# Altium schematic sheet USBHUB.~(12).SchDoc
size A
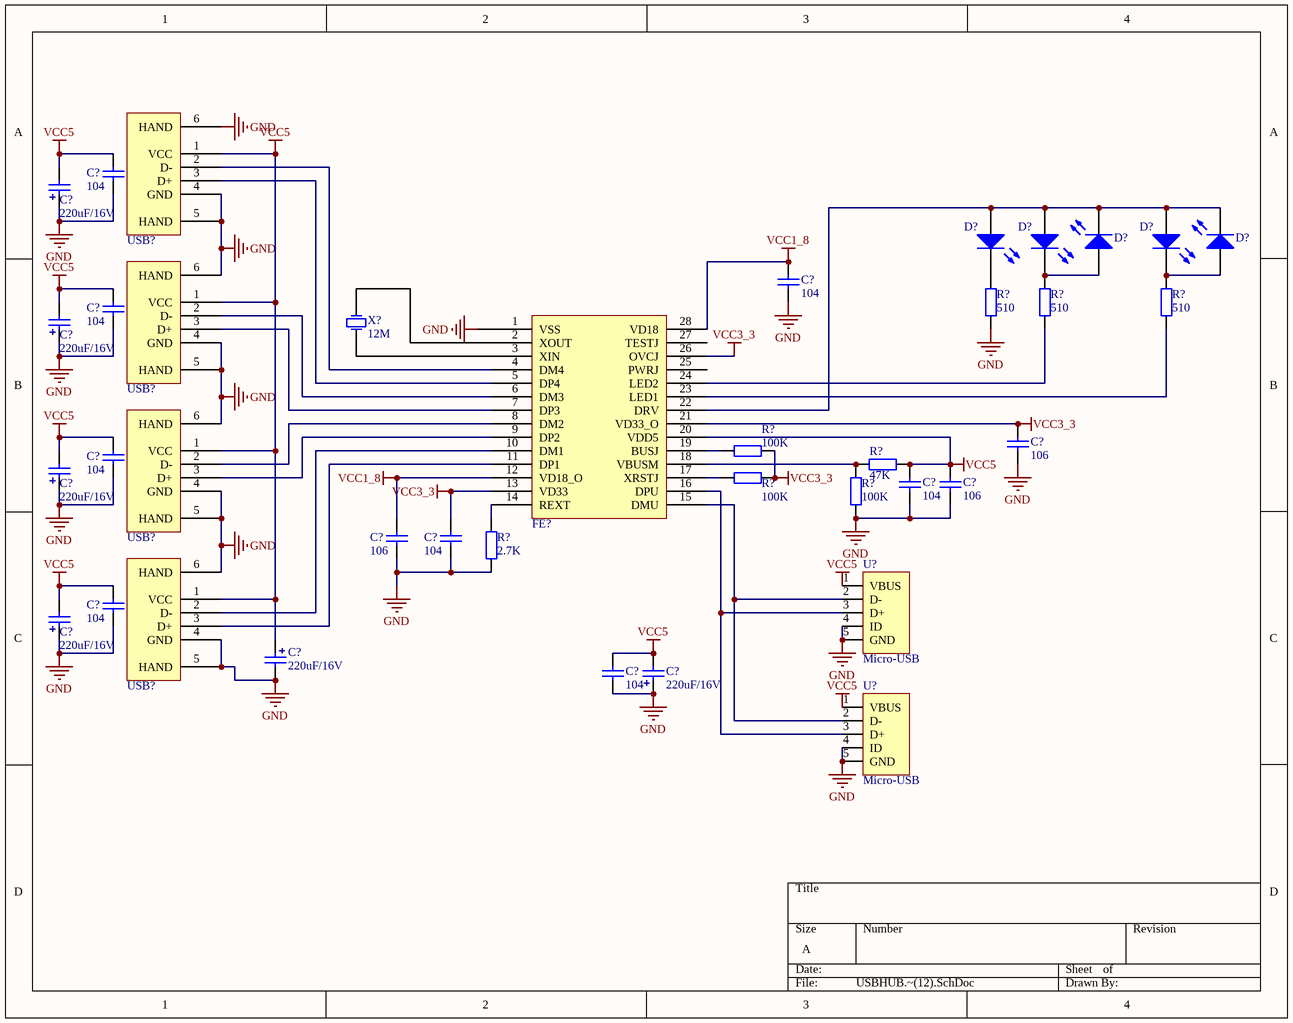
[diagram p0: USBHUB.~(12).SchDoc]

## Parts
(Parts that share a designator on the sheet are numbered #1, #2 ... from top to bottom, then left to right.)
C?#1  value 104  [0603]  (hidden comment: Cap1)
C?#2  value 220uF/16V  [cap_220uF/16V]  (hidden comment: Cap_Pol)
C?#3  value 104  [0603]  (hidden comment: Cap1)
C?#4  value 104  [0603]  (hidden comment: Cap1)
C?#5  value 220uF/16V  [cap_220uF/16V]  (hidden comment: Cap_Pol)
C?#6  value 106  [2012[0805]-C]  (hidden comment: Cap1)
C?#7  value 104  [0603]  (hidden comment: Cap1)
C?#8  value 220uF/16V  [cap_220uF/16V]  (hidden comment: Cap_Pol)
C?#9  value 104  [0603]  (hidden comment: Cap1)
C?#10  value 106  [2012[0805]-C]  (hidden comment: Cap1)
C?#11  value 106  [2012[0805]-C]  (hidden comment: Cap1)
C?#12  value 104  [0603]  (hidden comment: Cap1)
C?#13  value 104  [0603]  (hidden comment: Cap1)
C?#14  value 220uF/16V  [cap_220uF/16V]  (hidden comment: Cap_Pol)
C?#15  value 220uF/16V  [cap_220uF/16V]  (hidden comment: Cap_Pol)
C?#16  value 104  [0603]  (hidden comment: Cap1)
C?#17  value 220uF/16V  [cap_220uF/16V]  (hidden comment: Cap_Pol)
D?#1  LED  [0603-Polar]  (value not drawn)
D?#2  LED  [0603-Polar]  (value not drawn)
D?#3  LED  [0603-Polar]  (value not drawn)
D?#4  LED  [0603-Polar]  (value not drawn)
D?#5  LED  [0603-Polar]  (value not drawn)
FE?  FE1.1s  [SSOP-28]  (value not drawn)
R?#1  value 510  [0603]  (hidden comment: Res1)
R?#2  value 510  [0603]  (hidden comment: Res1)
R?#3  value 510  [0603]  (hidden comment: Res1)
R?#4  value 100K  [0603]  (hidden comment: Res1)
R?#5  value 47K  [0603]  (hidden comment: Res1)
R?#6  value 100K  [0603]  (hidden comment: Res1)
R?#7  value 100K  [0603]  (hidden comment: Res1)
R?#8  value 2.7K  [0603]  (hidden comment: Res1)
U?#1  Micro-USB  [Micro-USB]
U?#2  Micro-USB  [Micro-USB]
USB?#1  USB  [USB2.5-2V4A]  (value not drawn)
USB?#2  USB  [USB2.5-2V4A]  (value not drawn)
USB?#3  USB  [USB2.5-2V4A]  (value not drawn)
USB?#4  USB  [USB2.5-2V4A]  (value not drawn)
X?  12M  [XTAL_SMD]

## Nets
GND: C?#1.1 C?#2.1 C?#3.2 C?#4.1 C?#5.1 C?#6.1 C?#7.1 C?#8.1 C?#9.1 C?#10.1 C?#11.1 C?#12.1 C?#13.1 C?#14.1 C?#15.2 C?#16.1 C?#17.1 R?#1.1 R?#7.1 R?#8.1 U?#1.4(ID) U?#1.5(GND) U?#2.4(ID) U?#2.5(GND) USB?#1.4(GND) USB?#1.5(HAND) USB?#1.6(HAND) USB?#2.4(GND) USB?#2.5(HAND) USB?#2.6(HAND) USB?#3.4(GND) USB?#3.5(HAND) USB?#3.6(HAND) USB?#4.4(GND) USB?#4.5(HAND) USB?#4.6(HAND)
VCC1_8: C?#3.1 C?#11.2 FE?.12(VD18_O) FE?.28(VD18)
VCC3_3: C?#6.2 C?#12.2 FE?.13(VD33) FE?.21(VD33_O) FE?.26(OVCJ) R?#4.2 R?#6.2
VCC5: C?#1.2 C?#2.2 C?#4.2 C?#5.2 C?#7.2 C?#8.2 C?#9.2 C?#10.2 C?#13.2 C?#14.2 C?#15.1 C?#16.2 C?#17.2 FE?.20(VDD5) R?#5.2 U?#1.1(VBUS) U?#2.1(VBUS) USB?#1.1(VCC) USB?#2.1(VCC) USB?#3.1(VCC) USB?#4.1(VCC)
NetD?#1_1: D?#1.1(A) D?#2.1(A) D?#3.1(A) D?#4.2(K) D?#5.2(K) FE?.22(DRV)
NetD?#1_2: D?#1.2(K) R?#1.2
NetD?#2_2: D?#2.2(K) D?#4.1(A) R?#2.2
NetD?#3_2: D?#3.2(K) D?#5.1(A) R?#3.2
NetFE?_4: FE?.4(DM4) USB?#1.2(D-)
NetFE?_5: FE?.5(DP4) USB?#1.3(D+)
NetFE?_6: FE?.6(DM3) USB?#2.2(D-)
NetFE?_7: FE?.7(DP3) USB?#2.3(D+)
NetFE?_8: FE?.8(DM2) USB?#3.2(D-)
NetFE?_9: FE?.9(DP2) USB?#3.3(D+)
NetFE?_10: FE?.10(DM1) USB?#4.2(D-)
NetFE?_11: FE?.11(DP1) USB?#4.3(D+)
NetFE?_14: FE?.14(REXT) R?#8.2
NetFE?_15: FE?.15(DMU) U?#1.2(D-) U?#2.2(D-)
NetFE?_16: FE?.16(DPU) U?#1.3(D+) U?#2.3(D+)
NetFE?_17: FE?.17(XRSTJ) R?#6.1
NetFE?_18: FE?.18(VBUSM) R?#5.1 R?#7.2
NetFE?_19: FE?.19(BUSJ) R?#4.1
NetFE?_23: FE?.23(LED1) R?#3.1
NetFE?_24: FE?.24(LED2) R?#2.1

Not connected (* = marked no-connect by the designer): FE? 1(VSS) 2(XOUT) 3(XIN) 25(PWRJ) 27(TESTJ); X? 1(OSC1) 2(OSC2)

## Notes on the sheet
- Labels drawn without touching a wire or pin: GND

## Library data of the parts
C?#1 C?#3 C?#4 C?#6 C?#7 C?#9-C?#13 C?#16 = Cap1: Capacitor
C?#2 C?#5 C?#8 C?#14 C?#15 C?#17 = Cap_Pol: Capacitor
D?#1-D?#5 = LED1: Typical INFRARED GaAs LED
R?#1-R?#8 = Res1: Resistor
X? = XTAL_1: Crystal Oscillator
